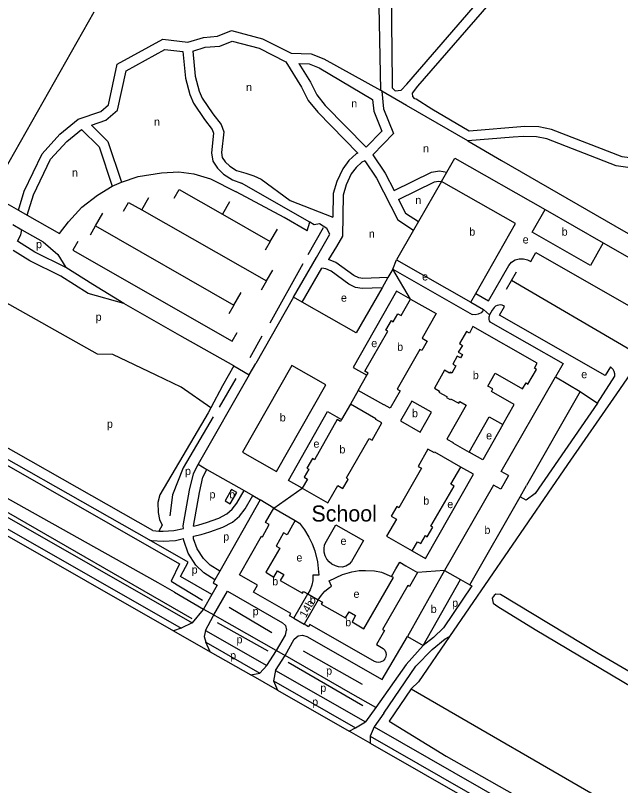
# Model space of a CAD drawing. Extents: x 157155 to 159285, y 385001 to 386651.
# Drawn here: x 157882.5 to 158185, y 385554.1 to 385939.1 of the extents above; entities that cross this region are included whole.
import ezdxf

# ---------------------------------------------------------------- set-up
doc = ezdxf.new("R2010")
doc.units = 0
for name, color, linetype in [('BLT_Basislijn', 7, 'Continuous'), ('BLT_Bebouwing', 7, 'Continuous'), ('BLT_Bebouwing_beschrifting', 7, 'Continuous'), ('BLT_Centroide', 7, 'Continuous'), ('BLT_Huisnummer', 7, 'Continuous'), ('BLT_Onderdoorgang_en_onderverdeling', 7, 'Continuous'), ('BLT_Onderverdeling_panden', 7, 'Continuous'), ('BLT_Vlakafsluiter', 7, 'Continuous')]:
    doc.layers.add(name, color=color, linetype=linetype)

msp = doc.modelspace()

# ---------------------------------------------------------------- linework, layer by layer
at = {"layer": 'BLT_Basislijn'}
for p, q in [((157921.7, 385940.64), (157870.02, 385849.72)), ((158065.64, 385901.19), (158064.92, 385901.61)), ((158077.89, 385894.08), (158065.64, 385901.19)), ((158108.59, 385876.35), (158077.89, 385894.08)), ((158108.59, 385876.35), (158125.46, 385866.62)), ((158125.46, 385866.62), (158182.09, 385833.86)), ((158095.46, 385856.11), (158098.05, 385860.64)), ((157930.9, 385853.76), (157935.5, 385855.78)), ((158029.57, 385835.71), (157995.41, 385855.27)), ((157870.02, 385849.72), (157883.97, 385841.75)), ((157945.6, 385841.82), (157949.12, 385848.02)), ((157989.49, 385845.91), (157985.95, 385839.71)), ((157883.97, 385841.75), (157888.42, 385839.21)), ((157945.6, 385841.82), (158008.02, 385806.36)), ((157888.42, 385839.21), (157904.48, 385830.02)), ((157922.52, 385833.85), (157926.17, 385840.17)), ((157881.26, 385834.49), (157885.77, 385831.91)), ((158028.3, 385831.37), (158029.57, 385835.71)), ((158031.86, 385834.39), (158029.57, 385835.71)), ((157920.05, 385829.45), (157922.52, 385833.85)), ((157922.52, 385833.85), (157991.7, 385794.31)), ((158009.9, 385826.03), (158013.52, 385832.24)), ((158036.38, 385832.81), (158028.61, 385819.35)), ((158182.09, 385833.86), (158189.94, 385829.31)), ((158032.96, 385818.08), (158039.63, 385829.66)), ((157639.53, 385824.67), (157970.82, 385635.41)), ((158009.9, 385826.03), (158007.39, 385821.71)), ((158176.35, 385825.36), (158211.94, 385805.05)), ((157636.02, 385820.91), (157965.4, 385632.75)), ((157635.36, 385817.84), (157961.55, 385631.5)), ((158026.08, 385814.96), (158009.73, 385785.26)), ((158021.53, 385798.27), (158032.96, 385818.08)), ((158071.13, 385812.23), (158073.04, 385816.9)), ((158008.02, 385806.36), (158011.09, 385811.73)), ((158071.13, 385812.23), (158110.75, 385789.6)), ((158130.52, 385806.51), (158133.01, 385810.84)), ((158008.02, 385806.36), (158005.34, 385801.67)), ((158128.03, 385802.17), (158130.52, 385806.51)), ((158190.3, 385771.65), (158130.52, 385806.51)), ((157991.7, 385794.31), (157995.3, 385800.62)), ((158021.53, 385798.27), (158002.58, 385765.1)), ((157991.7, 385794.31), (157989.18, 385789.94)), ((157999.77, 385768.12), (158005.86, 385778.96)), ((157991.66, 385763.92), (157985.91, 385753.84)), ((157991.66, 385763.92), (157999.37, 385759.49)), ((157984.55, 385743.21), (157992.81, 385757.65)), ((158164.76, 385751.04), (158173.39, 385745.33)), ((157809.98, 385730.26), (157970.64, 385637.67)), ((157961.94, 385650.75), (157953.87, 385655.46)), ((157989.31, 385643.27), (158010.69, 385630.68)), ((157970.82, 385635.41), (157965.4, 385632.75)), ((157983.3, 385635.7), (158008.64, 385621.53)), ((157965.4, 385632.75), (157961.55, 385631.5)), ((157961.55, 385631.5), (157979.88, 385621.02)), ((157977.48, 385631.61), (158008.14, 385614.09)), ((157977.71, 385625.72), (158004.73, 385610.28)), ((157979.88, 385621.02), (157977.71, 385625.72)), ((157979.88, 385621.02), (158000.13, 385609.46)), ((158008.14, 385614.09), (158012.96, 385621.67)), ((158012.49, 385611.61), (158017.24, 385619.09)), ((158012.96, 385621.67), (158017.24, 385619.09)), ((158050, 385600.34), (158017.24, 385619.09)), ((158026.32, 385621.5), (158055.88, 385604.73)), ((158056.11, 385594.04), (158018.85, 385615.72)), ((158004.73, 385610.28), (158008.14, 385614.09)), ((158012.49, 385611.61), (158011.52, 385606.4)), ((158012.49, 385611.61), (158057.5, 385585.9)), ((158000.13, 385609.46), (158004.73, 385610.28)), ((158013.49, 385601.82), (158000.13, 385609.46)), ((158011.52, 385606.4), (158052.53, 385582.98)), ((158011.52, 385606.4), (158013.49, 385601.82)), ((158013.49, 385601.82), (158049.3, 385581.36)), ((158062.62, 385593.13), (158050, 385600.34)), ((158066.7, 385590.24), (158061.86, 385583.4)), ((158052.53, 385582.98), (158057.5, 385585.9)), ((158049.3, 385581.36), (158052.53, 385582.98)), ((158059.74, 385575.4), (158049.3, 385581.36)), ((158061.86, 385583.4), (158059.85, 385578.79)), ((158061.86, 385583.4), (158520.35, 385321.48)), ((158059.85, 385578.79), (158059.74, 385575.4)), ((158059.85, 385578.79), (158517.55, 385317.32)), ((158059.74, 385575.4), (158513.56, 385316.15))]:
    msp.add_line(p, q, dxfattribs=at)
for points in [[(158193.1, 385867.29), (158185.83, 385868.38), (158150.52, 385881.99), (158144.16, 385883.41), (158137.07, 385883.49), (158109.24, 385881.23), (158090.69, 385892.15), (158082.84, 385897.12), (158082.12, 385897.33), (158081.13, 385898.52), (158081.04, 385900.21), (158083.69, 385903.74), (158232.85, 386075.43)], [(158058.11, 385998.84), (158065.66, 385977.32), (158069.48, 385961.42), (158070.35, 385950.92), (158070.72, 385905.52), (158070.86, 385902.92), (158072.24, 385901.36), (158075.28, 385901.73), (158078.07, 385904.64), (158159.39, 385998.88), (158196.7, 386040.52), (158202.31, 386047.31), (158203.32, 386049.14), (158203.32, 386049.93), (158202.05, 386051.38), (158201.25, 386051.54), (158124.6, 386056.77), (158090.77, 386058.91)], [(158050, 386000.01), (158053.57, 385992.27), (158058.08, 385979.83), (158059.78, 385974.14), (158062.8, 385960.62), (158063.91, 385952.21), (158064.92, 385901.61)], [(158200.52, 385941.84), (158208.01, 385928.88), (158208.95, 385926.59), (158209.39, 385924.65), (158209.9, 385914.88), (158220.72, 385883.17), (158220.72, 385876.56), (158219.13, 385873.06), (158217.85, 385871.47), (158209.84, 385864.79), (158206.28, 385863.13), (158202.27, 385861.94), (158196.93, 385861.79), (158182.8, 385863.93), (158148.04, 385877.29), (158142.95, 385878.4), (158136.37, 385878.52), (158131.24, 385878.28), (158108.59, 385876.35)], [(157883.97, 385841.75), (157886.87, 385851.28), (157895.9, 385869.94), (157904.67, 385879.72), (157913.82, 385887.12), (157925.15, 385891.03), (157928.97, 385894.4), (157933.41, 385914.71), (157956.13, 385927.22), (157968.74, 385925.73), (157976.46, 385928.06), (157983.43, 385928.62), (157990.48, 385931.45), (158006.05, 385927.35), (158020.27, 385920.14), (158030.27, 385919.83), (158036.57, 385917.29), (158064.92, 385901.61)], [(157971.23, 385921.26), (157977.39, 385923.12), (157984.58, 385923.7), (157990.8, 385926.19), (158004.26, 385922.65), (158017.69, 385915.84)], [(157920.54, 385884.15), (157927.71, 385886.62), (157933.5, 385891.73), (157937.81, 385911.43), (157957.14, 385922.07), (157966.24, 385920.99)], [(157966.24, 385920.99), (157967.42, 385907.74), (157969.68, 385899.59), (157971.47, 385895.24), (157977.06, 385886.98), (157980.87, 385882.02), (157981.56, 385880.25), (157980.46, 385870.35), (157981.14, 385866.15), (157983.43, 385862.73), (157986.46, 385859.76), (157990.95, 385856.88), (157995.41, 385855.27)], [(157971.23, 385921.26), (157972.36, 385908.63), (157974.41, 385901.21), (157975.89, 385897.62), (157981.12, 385889.91), (157985.27, 385884.5), (157986.67, 385880.92), (157985.5, 385870.48), (157985.9, 385868.03), (157987.3, 385865.94), (157989.6, 385863.69), (157992.99, 385861.51), (157997.71, 385860.26), (158001.71, 385858.94), (158005.39, 385857.15), (158019.82, 385846.55), (158041.19, 385838.22)], [(158017.69, 385915.84), (158025.56, 385903.17), (158028.86, 385896.58), (158033.65, 385890.64), (158053.58, 385870.27)], [(158024.09, 385915.02), (158029.93, 385905.61), (158033.09, 385899.3), (158037.39, 385893.97), (158057.78, 385873.12)], [(158024.09, 385915.02), (158029.23, 385914.86), (158034.35, 385912.8), (158061.05, 385897.02), (158061.65, 385891.16), (158065.61, 385881.14), (158057.78, 385873.12)], [(158065.64, 385901.19), (158066.55, 385892.35), (158071.45, 385879.97), (158061.13, 385869.41)], [(157920.54, 385884.15), (157928.72, 385876.02), (157935.5, 385855.78)], [(157888.42, 385839.21), (157891.54, 385849.45), (157900.09, 385867.13), (157908.13, 385876.08), (157915.53, 385882.07)], [(157915.53, 385882.07), (157924.35, 385873.31), (157930.9, 385853.76)], [(158053.58, 385870.27), (158052.88, 385869.92), (158049.08, 385866.48), (158046.07, 385862.42), (158043.08, 385856.1), (158041.39, 385850.01), (158041.19, 385838.22)], [(158061.13, 385869.41), (158067.27, 385860.23), (158071.72, 385851.49)], [(158057.11, 385866.43), (158055.71, 385865.74), (158052.81, 385863.11), (158050.38, 385859.83), (158047.78, 385854.35), (158046.38, 385849.28), (158046.02, 385828.75), (158043.03, 385823.48), (158039.04, 385817.11)], [(158057.11, 385866.43), (158062.95, 385857.69), (158073.59, 385836.8), (158081.48, 385831.67)], [(158098.05, 385860.64), (158102.12, 385867.78), (158147.25, 385842.03)], [(157935.5, 385855.78), (157943.83, 385858.58), (157955.42, 385860.38), (157964.23, 385860.84), (157971.59, 385859.9), (157980.06, 385857.31), (157992.9, 385850.94)], [(158071.72, 385851.49), (158090.39, 385860.73), (158094.52, 385861.36), (158098.05, 385860.64)], [(157904.48, 385830.02), (157908.97, 385835.93), (157915.62, 385843.21), (157923.49, 385849.16), (157930.9, 385853.76)], [(158073.99, 385847.04), (158091.91, 385855.9), (158093.92, 385856.21), (158095.46, 385856.11)], [(157961.9, 385847.69), (157964.37, 385852.05), (157985.95, 385839.71)], [(158028.3, 385831.37), (158016.76, 385838.11), (157992.9, 385850.94)], [(157936.44, 385841.22), (157938.93, 385845.61), (157945.6, 385841.82)], [(158073.99, 385847.04), (158077.44, 385840.27), (158083.97, 385836.01)], [(157985.95, 385839.71), (158009.9, 385826.03)], [(157664.14, 385836.65), (157964.44, 385664.94), (157960.27, 385656.22), (157975.98, 385646.81)], [(158039.63, 385829.66), (158038.17, 385832.5), (158034.49, 385834.94), (158031.86, 385834.39)], [(157883.57, 385826.16), (157885.12, 385829.39), (157885.77, 385831.91)], [(157885.77, 385831.91), (157896.27, 385825.9), (157903.6, 385819.54), (157907.66, 385813.06)], [(158233.54, 385829.94), (158219.28, 385802.69), (158182.95, 385750), (158158.41, 385714.59), (158099.54, 385628.64)], [(157907.66, 385813.06), (157892.22, 385820.69), (157883.57, 385826.16)], [(157913.71, 385826.09), (157911.21, 385821.76), (157990.79, 385776.27), (157993.26, 385780.58)], [(157936.64, 385795.09), (157918.91, 385800.1), (157905.22, 385808.69), (157889.77, 385816.32), (157881.38, 385821.62)], [(158140.09, 385816.1), (158142.59, 385820.59), (158197.07, 385789.42)], [(158068.7, 385807.99), (158056.14, 385807.54), (158054.09, 385807.9), (158051.71, 385809.08), (158042.7, 385815.61), (158039.04, 385817.11)], [(158119.02, 385796.48), (158129.09, 385814.13), (158130.52, 385815.7), (158132.3, 385816.85), (158134.34, 385817.42), (158136.46, 385817.47), (158138.51, 385816.94), (158140.09, 385816.1)], [(157936.64, 385795.09), (157921.14, 385804.6), (157907.66, 385813.06)], [(158025.87, 385795.79), (158035.63, 385812.7)], [(158065.77, 385802.88), (158055.79, 385802.52), (158052.52, 385803.1), (158049.11, 385804.78), (158040.25, 385811.21), (158037.58, 385812.31), (158035.63, 385812.7)], [(158071.13, 385812.23), (158068.7, 385807.99)], [(158068.7, 385807.99), (158065.77, 385802.88)], [(157980.12, 385742.87), (157965.34, 385753.22), (157952.85, 385759.3), (157931.21, 385769.57), (157923.59, 385769.74), (157871.53, 385798.9), (157868.14, 385803.38)], [(158065.77, 385802.88), (158052.87, 385780.34), (158025.87, 385795.79)], [(158079.92, 385797.29), (158073.02, 385801.15), (158051.23, 385763.09), (158058.19, 385759.17)], [(158112.54, 385800.09), (158119.02, 385796.48)], [(158025.87, 385795.79), (158021.53, 385798.27)], [(158110.06, 385795.75), (158116.53, 385792.14)], [(157991.66, 385763.92), (157964.59, 385779.05), (157936.64, 385795.09)], [(158116.53, 385792.14), (158116.16, 385791.43), (158115.23, 385790.48), (158113.8, 385789.72), (158112.28, 385789.32), (158110.75, 385789.6)], [(158127.03, 385793.64), (158126.42, 385793.93), (158125.77, 385794.15), (158124.93, 385794.34), (158124.07, 385794.29), (158123.23, 385794.07), (158122.46, 385793.69), (158121.79, 385793.15), (158120.87, 385791.8), (158119.44, 385789.32)], [(158177.34, 385759.02), (158124.51, 385789.18), (158127.03, 385793.64)], [(158119.44, 385789.32), (158119.21, 385788.78), (158119.08, 385788.21), (158119.06, 385787.62), (158119.15, 385787.04), (158119.34, 385786.48), (158119.63, 385785.97), (158119.89, 385785.66), (158156.25, 385765.12), (158152.37, 385758.43)], [(158173.39, 385745.33), (158182.15, 385758.68), (158182.13, 385759.93), (158181.8, 385761.14), (158181.26, 385762.13), (158180.48, 385762.95), (158179.88, 385763.41), (158177.34, 385759.02)], [(157999.37, 385759.49), (157973.79, 385714.72)], [(157985.91, 385753.84), (157980.12, 385742.87)], [(157951.23, 385681.58), (157844.91, 385742), (157842.44, 385743.41)], [(157980.12, 385742.87), (157978.81, 385740.37), (157966.22, 385718.98), (157954.68, 385699.37), (157953.69, 385695.67), (157953.78, 385690.56), (157954.5, 385687.07), (157955.81, 385684.24), (157954.17, 385681.36)], [(158173.39, 385745.33), (158142.21, 385700.17), (158137.75, 385696.74), (158134.71, 385698.52)], [(157953.87, 385655.46), (157874.22, 385700), (157806.93, 385738.71)], [(157949.38, 385676.88), (157842.44, 385737.65), (157838.31, 385740)], [(157981.4, 385738.39), (157966.39, 385712.87), (157960.96, 385699.4), (157959.63, 385688.87)], [(158025.88, 385702.73), (158019.06, 385706.55), (158038.44, 385741.15), (158045.5, 385737.03)], [(158126.09, 385734.6), (158116.14, 385716.93), (158109.27, 385720.8)], [(157966.42, 385682.68), (157966.38, 385684.02), (157969.54, 385701.69), (157971.51, 385709.92), (157973.79, 385714.72)], [(157973.79, 385714.72), (157978.23, 385712.18)], [(157971.42, 385683.81), (157974.44, 385700.66), (157976.24, 385708.2), (157978.23, 385712.18)], [(157978.23, 385712.18), (157996.8, 385701.57)], [(158080.81, 385671.45), (158087.53, 385667.63), (158111.44, 385709.71), (158105.07, 385713.33)], [(157971.42, 385683.81), (157974.09, 385684.41), (157978.06, 385685.65), (157984.1, 385687.83), (157988.1, 385689.97), (157990.85, 385692.27), (157993.23, 385695.31), (157996.8, 385701.57)], [(157996.8, 385701.57), (158001.14, 385699.08)], [(157971.54, 385678.71), (157975.39, 385679.58), (157979.65, 385680.91), (157986.14, 385683.25), (157990.91, 385685.8), (157994.46, 385688.78), (157997.39, 385692.51), (158001.14, 385699.08)], [(158004.89, 385696.94), (157984.61, 385661.28)], [(158001.14, 385699.08), (158004.89, 385696.94)], [(158022.37, 385686.65), (158024.49, 385685.34), (158027.01, 385681.98), (158029.15, 385678.36), (158030.82, 385674.94), (158032.16, 385671.38), (158033.41, 385666.01), (158034.2, 385659.33), (158031.16, 385659.21), (158031.08, 385656.54), (158030.62, 385654.22), (158029.81, 385652.01), (158028.57, 385649.99)], [(157951.23, 385681.58), (157954.17, 385681.36)], [(157954.17, 385681.36), (157956.29, 385681.21), (157961.7, 385681.61), (157966.42, 385682.68)], [(157949.38, 385676.88), (157950.5, 385676.62), (157956.29, 385676.2), (157962.44, 385676.65), (157966.58, 385677.58)], [(157980.61, 385649.59), (157964.92, 385658.7), (157968.85, 385665.81), (157949.38, 385676.88)], [(157982.14, 385656.93), (157976.67, 385660.41), (157972.66, 385664.34), (157968.77, 385670.24), (157966.61, 385676.56), (157966.58, 385677.58)], [(157984.61, 385661.28), (157979.79, 385664.35), (157976.54, 385667.54), (157973.29, 385672.46), (157971.58, 385677.47), (157971.54, 385678.71)], [(157984.61, 385661.28), (157982.14, 385656.93)], [(158033.82, 385646.98), (158035.43, 385649.3), (158037.14, 385651.24), (158039.55, 385653.13), (158040.56, 385653.75), (158039.28, 385656.45), (158045.91, 385659.54), (158050.61, 385660.93), (158054.25, 385661.58), (158057.49, 385661.7), (158061.93, 385661.52), (158065.43, 385660.86), (158070.52, 385658.7)], [(157982.14, 385656.93), (157981.29, 385655.43), (157983.26, 385654.23), (157980.61, 385649.59)], [(158109.57, 385654.49), (158110.55, 385653.93), (158096.4, 385633.02), (158091.52, 385628.16), (158086.24, 385624.14)], [(157961.94, 385650.75), (157976.49, 385642.37)], [(157980.61, 385649.59), (157976.49, 385642.37)], [(157981.67, 385639.39), (157988.47, 385651.24), (158015.98, 385635.49), (158017.47, 385634.05), (158018.04, 385631.75)], [(158236.55, 385583.42), (158173.84, 385620.11), (158125.02, 385649.58), (158122.65, 385649.77), (158121.81, 385649.07), (158120.86, 385647.83), (158121.3, 385645.21), (158123.55, 385643.56), (158142.2, 385632.08), (158207.94, 385593.09)], [(157976.49, 385642.37), (157976.38, 385642.17), (157970.82, 385635.41)], [(157976.49, 385642.37), (157981.67, 385639.39)], [(157977.48, 385631.61), (157981.53, 385639.14), (157981.67, 385639.39)], [(157981.67, 385639.39), (157982.16, 385639.11)], [(157982.16, 385639.11), (157983.29, 385638.46), (158012.61, 385621.86), (158012.96, 385621.67)], [(157977.48, 385631.61), (157976.88, 385628.59), (157977.71, 385625.72)], [(158012.96, 385621.67), (158017.44, 385629.31), (158018.04, 385631.75)], [(158017.24, 385619.09), (158021.89, 385627.33), (158023.74, 385628.9)], [(158023.74, 385628.9), (158025.97, 385629.29), (158028.16, 385628.56), (158065.73, 385607.11), (158078.47, 385628.58)], [(158066.7, 385590.24), (158082.68, 385613.8), (158090.81, 385622.14), (158097.3, 385627.48), (158099.54, 385628.64)], [(158099.54, 385628.64), (158084.03, 385605.99), (158080.36, 385602.55)], [(158086.24, 385624.14), (158077.81, 385614.6), (158062.62, 385593.13)], [(158080.36, 385602.55), (158069.23, 385586.39), (158097.78, 385568.87), (158181.11, 385521.64)], [(158080.36, 385602.55), (158285.26, 385483.93), (158335.7, 385455.5), (158372.47, 385434.35)], [(158062.62, 385593.13), (158057.5, 385585.9)]]:
    msp.add_lwpolyline(points, dxfattribs=at)
msp.add_lwpolyline([(158042.65, 385684.41), (158056.41, 385676.58), (158050.49, 385666.2), (158049.24, 385664.79), (158047.63, 385663.79), (158045.8, 385663.32), (158044.04, 385663.38), (158042.46, 385663.9), (158040.7, 385664.78), (158039.27, 385665.91), (158038.13, 385667.33), (158037.3, 385668.96), (158036.83, 385670.72), (158036.75, 385672.54), (158037.02, 385674.34), (158037.29, 385675.11)], close=True, dxfattribs=at)
at = {"layer": 'BLT_Bebouwing'}
for p, q in [((158095.46, 385856.11), (158083.97, 385836.01)), ((158081.48, 385831.67), (158073.04, 385816.9)), ((158152.37, 385758.43), (158164.76, 385751.04)), ((158164.76, 385751.04), (158137.87, 385704.04)), ((158134.71, 385698.52), (158137.87, 385704.04)), ((158097.01, 385661.64), (158078.47, 385628.58)), ((158086.24, 385624.14), (158104.97, 385657.1)), ((158028.57, 385649.99), (158033.82, 385646.98)), ((158021.59, 385637.73), (158026.76, 385634.73)), ((158078.47, 385628.58), (158086.24, 385624.14))]:
    msp.add_line(p, q, dxfattribs=at)
for points in [[(158112.54, 385800.09), (158132.46, 385835), (158095.46, 385856.11)], [(158176.35, 385825.36), (158169.95, 385814.11), (158140.81, 385830.77), (158147.25, 385842.03)], [(158147.25, 385842.03), (158176.35, 385825.36)], [(158083.97, 385836.01), (158081.48, 385831.67)], [(158073.04, 385816.9), (158110.06, 385795.75)], [(158110.06, 385795.75), (158112.54, 385800.09)], [(158079.92, 385797.29), (158092.73, 385790), (158085.74, 385777.77), (158088.32, 385776.3), (158085.6, 385771.54), (158084.65, 385772.08), (158073.29, 385752.19), (158074.77, 385751.34), (158069.84, 385742.68), (158066.74, 385744.49), (158066.66, 385744.35), (158053.88, 385751.66)], [(158058.19, 385759.17), (158058.8, 385760.24), (158057.17, 385761.17), (158068.65, 385781.2), (158067.7, 385781.75), (158070.42, 385786.5), (158071.37, 385785.96), (158073.64, 385789.98), (158075.27, 385789.06), (158079.92, 385797.29)], [(158126.09, 385734.6), (158131.78, 385744.59), (158120.45, 385751.04), (158121.14, 385752.34), (158118.66, 385753.74), (158122.31, 385760.21), (158136.02, 385752.41), (158137.71, 385755.37), (158138.68, 385754.8), (158142.91, 385762.11), (158141.89, 385762.71), (158143.33, 385765.24), (158111.17, 385783.55), (158109.47, 385780.19), (158107.98, 385781.09), (158104.49, 385775.03), (158105.95, 385774.12), (158103.87, 385770.72), (158105.89, 385769.57), (158104.92, 385767.86), (158103.34, 385768.69), (158101.12, 385764.73), (158102.64, 385763.85), (158100.62, 385760.28), (158099.76, 385760.77), (158099.48, 385760.29), (158096.99, 385761.7), (158091.9, 385752.72), (158094.39, 385751.31), (158094.12, 385750.83), (158098.19, 385748.52), (158097.92, 385748.04), (158099.73, 385747.01), (158100, 385747.49), (158104.07, 385745.18), (158104.56, 385746.04), (158107.72, 385744.25), (158098.15, 385727.34), (158101.28, 385725.56), (158101.18, 385725.39), (158109.27, 385720.8)], [(158053.88, 385751.66), (158058.19, 385759.17)], [(158128.94, 385709.15), (158125.32, 385711.03), (158152.37, 385758.43)], [(158025.88, 385702.73), (158038.68, 385695.44), (158043.6, 385704.03), (158046.17, 385702.56), (158048.81, 385707.17), (158047.95, 385707.87), (158059.25, 385727.62), (158060.75, 385726.72), (158065.68, 385735.39), (158062.57, 385737.17), (158062.72, 385737.43), (158049.91, 385744.72)], [(158049.91, 385744.72), (158045.5, 385737.03)], [(158109.27, 385720.8), (158119.27, 385738.47), (158126.09, 385734.6)], [(158045.5, 385737.03), (158044.99, 385736.13), (158043.37, 385737.05), (158031.9, 385717), (158030.94, 385717.55), (158028.22, 385712.79), (158029.17, 385712.24), (158026.88, 385708.24), (158028.5, 385707.31), (158025.88, 385702.73)], [(158105.07, 385713.33), (158092.16, 385720.68), (158092.01, 385720.42), (158088.7, 385722.3), (158083.77, 385713.64), (158085.41, 385712.71), (158074.07, 385693), (158073.11, 385693.55), (158070.38, 385688.8), (158072.94, 385687.33), (158068, 385678.74), (158080.81, 385671.45)], [(158080.81, 385671.45), (158083.46, 385676.01), (158085.07, 385675.07), (158087.39, 385679.07), (158088.34, 385678.52), (158091.1, 385683.28), (158090.15, 385683.83), (158101.73, 385703.8), (158100.1, 385704.75), (158105.07, 385713.33)], [(158128.94, 385709.15), (158125.08, 385702.21), (158121.4, 385704.31), (158097.01, 385661.64)], [(158109.57, 385654.49), (158134.71, 385698.52)], [(157994.42, 385659.4), (158005.48, 385678.76), (158005.92, 385678.51), (158009.37, 385684.61), (158007.52, 385685.66), (158011.59, 385692.81)], [(158011.59, 385692.81), (158022.37, 385686.65)], [(158021.05, 385684.33), (158018.3, 385679.51), (158016.53, 385680.51), (158012.84, 385673.84), (158014.63, 385672.85), (158007.59, 385660.71), (158011.7, 385658.36), (158013.46, 385661.42), (158016.58, 385659.63), (158014.83, 385656.57), (158025.95, 385650.22), (158026.5, 385651.18), (158028.57, 385649.99)], [(158022.37, 385686.65), (158021.05, 385684.33)], [(158072.68, 385662.46), (158074.56, 385665.75), (158077.69, 385663.96)], [(158070.52, 385658.7), (158072.68, 385662.46)], [(158077.69, 385663.96), (158083.52, 385660.64)], [(158021.59, 385637.73), (158019.41, 385639), (158020.09, 385640.17), (158001.53, 385650.78), (158003.5, 385654.21), (157994.42, 385659.4)], [(158083.52, 385660.64), (158079.49, 385653.59), (158078.6, 385654.1), (158066.01, 385632.06), (158066.91, 385631.55), (158062.93, 385624.57), (158066.32, 385622.63), (158067.1, 385621.79), (158067.62, 385620.71), (158067.78, 385619.52), (158067.69, 385618.76), (158067.47, 385618.06), (158067.13, 385617.44), (158066.67, 385616.87), (158066.08, 385616.37), (158065.56, 385616.08), (158064.8, 385615.81), (158063.81, 385615.7), (158063.05, 385615.79), (158062.03, 385616.17), (158029.62, 385634.71), (158028.91, 385633.49), (158026.76, 385634.73)], [(158033.82, 385646.98), (158035.91, 385645.78), (158035.36, 385644.82), (158047.52, 385637.93), (158049.23, 385640.95), (158052.53, 385639.07), (158050.78, 385636), (158056.69, 385632.46), (158071.44, 385658.17), (158070.52, 385658.7)], [(158104.97, 385657.1), (158109.57, 385654.49)]]:
    msp.add_lwpolyline(points, dxfattribs=at)
for points in [[(158037.61, 385754.34), (158020.65, 385764.04), (157995.92, 385720.81), (158012.93, 385711.1)], [(158080.64, 385746.26), (158075.01, 385736.4), (158084.77, 385730.75), (158090.43, 385740.68)], [(157990.52, 385702.1), (157987.29, 385696.4), (157989.87, 385694.93), (157993.1, 385700.63)]]:
    msp.add_lwpolyline(points, close=True, dxfattribs=at)
at = {"layer": 'BLT_Onderdoorgang_en_onderverdeling'}
for p, q in [((158021.59, 385637.73), (158028.57, 385649.99)), ((158033.82, 385646.98), (158026.76, 385634.73))]:
    msp.add_line(p, q, dxfattribs=at)
at = {"layer": 'BLT_Onderverdeling_panden'}
msp.add_lwpolyline([(158097.01, 385661.64), (158104.97, 385657.1)], dxfattribs=at)
at = {"layer": 'BLT_Vlakafsluiter'}
for p, q in [((158079.92, 385797.29), (158071.13, 385812.23)), ((158116.53, 385792.14), (158119.44, 385789.32)), ((157999.37, 385759.49), (158002.58, 385765.1)), ((158053.88, 385751.66), (158049.91, 385744.72)), ((158011.59, 385692.81), (158025.88, 385702.73)), ((158011.59, 385692.81), (158004.89, 385696.94)), ((158097.01, 385661.64), (158083.52, 385660.64))]:
    msp.add_line(p, q, dxfattribs=at)

# ---------------------------------------------------------------- texts
at = {"layer": 'BLT_Bebouwing_beschrifting'}
msp.add_text('School', height=8, dxfattribs=at).set_placement((158030.46, 385686.1))
at = {"layer": 'BLT_Centroide'}
for s, p in [('n', (157997.77, 385901.21)), ('n', (158050.33, 385893.07)), ('n', (157951.74, 385883.91)), ('n', (158086.24, 385870.54)), ('n', (157910.75, 385858.48)), ('n', (158082.37, 385844.77)), ('n', (158059.14, 385827.95)), ('b', (158109.35, 385828.97)), ('b', (158155.54, 385828.97)), ('e', (158136.03, 385825.06)), ('p', (157892.79, 385822.73)), ('e', (158085.77, 385806.57)), ('e', (158045.21, 385795.96)), ('p', (157922.6, 385786.4)), ('e', (158060.35, 385773.25)), ('b', (158073.3, 385771.39)), ('b', (158111.1, 385757.24)), ('e', (158165.31, 385757.72)), ('b', (158080.73, 385738.22)), ('b', (158014.62, 385736.12)), ('p', (157928.23, 385732.94)), ('e', (158117.76, 385727.13)), ('e', (158031.46, 385723)), ('b', (158044.44, 385720.14)), ('p', (157967.26, 385709.35)), ('p', (157979.48, 385697.67)), ('b', (157989.32, 385697.66)), ('b', (158086.36, 385694.53)), ('e', (158098.36, 385692.79)), ('b', (158116.93, 385679.89)), ('p', (157986.33, 385676.58)), ('e', (158044.98, 385674.42)), ('e', (158022.94, 385666.1)), ('p', (157970.59, 385660.05)), ('b', (158010.86, 385654.19)), ('b', (158029.61, 385644.92)), ('e', (158051.48, 385647.95)), ('p', (158100.78, 385643.45)), ('p', (158001.08, 385639.25)), ('b', (158090.08, 385640.38)), ('b', (158047.31, 385633.78)), ('p', (157992.99, 385625.19)), ('p', (157989.8, 385617.22)), ('p', (158037.79, 385609.57)), ('p', (158034.9, 385600.96)), ('p', (158030.8, 385594.05))]:
    msp.add_text(s, height=4, dxfattribs=at).set_placement(p)
at = {"layer": 'BLT_Huisnummer'}
msp.add_text('14b', height=4, rotation=60.128, dxfattribs=at).set_placement((158027.62, 385637.68))

doc.saveas('drawing.dxf')
